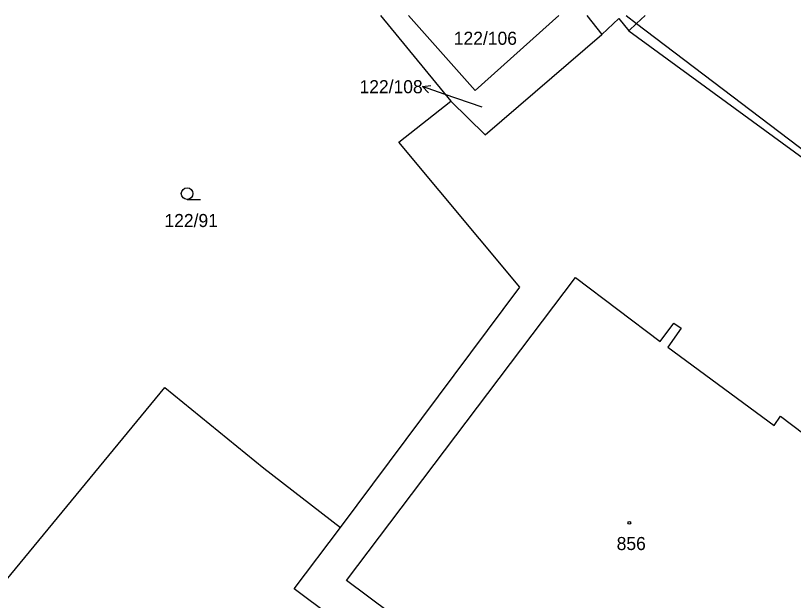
# Model space of a CAD drawing. Extents: x -805057 to -804930, y -994399 to -994240.
# Drawn here: x -804999.86 to -804979.61, y -994258.38 to -994243.17 of the extents above; entities that cross this region are included whole.
import ezdxf

# ---------------------------------------------------------------- set-up
doc = ezdxf.new("R2010")
doc.units = 0
doc.layers.add('Katastralni mapa', color=7, linetype='Continuous')

msp = doc.modelspace()

# ---------------------------------------------------------------- linework, layer by layer
at = {"layer": 'Katastralni mapa'}
for points in [[(-804990.359, -994243.17), (-804988.53, -994245.4)], [(-804987.89, -994245.12), (-804989.625, -994243.17)], [(-804987.89, -994245.12), (-804985.714, -994243.17)], [(-804984.989, -994243.17), (-804984.6, -994243.66)], [(-804983.965, -994243.17), (-804983.69, -994243.38)], [(-804983.69, -994243.38), (-804983.469, -994243.17)], [(-804984.6, -994243.66), (-804984.15, -994243.25)], [(-804984.15, -994243.25), (-804983.89, -994243.57)], [(-804983.89, -994243.57), (-804983.69, -994243.38)], [(-804983.69, -994243.38), (-804969.78, -994253.93)], [(-804983.89, -994243.57), (-804976.36, -994249.06)], [(-804987.63, -994246.27), (-804984.6, -994243.66)], [(-804989.11, -994245.175), (-804989.267, -994245.015), (-804989.046, -994244.985)], [(-804988.7, -994245.21), (-804989.267, -994245.015)], [(-804989.88, -994246.46), (-804988.53, -994245.4)], [(-804987.71, -994245.55), (-804988.7, -994245.21)], [(-804988.53, -994245.4), (-804987.63, -994246.27)], [(-804986.73, -994250.23), (-804989.88, -994246.46)], [(-804995.39, -994247.95), (-804995.039, -994247.95)], [(-804991.24, -994257.86), (-804985.28, -994249.98)], [(-804985.28, -994249.98), (-804983.08, -994251.65)], [(-804991.4, -994256.48), (-804986.73, -994250.23)], [(-804983.08, -994251.65), (-804982.72, -994251.17)], [(-804982.72, -994251.17), (-804982.53, -994251.3)], [(-804982.53, -994251.3), (-804982.88, -994251.79)], [(-804982.88, -994251.79), (-804980.11, -994253.83)], [(-805000.1, -994257.85), (-804995.97, -994252.84)], [(-804995.97, -994252.84), (-804993.39, -994254.94)], [(-804980.11, -994253.83), (-804979.95, -994253.59)], [(-804979.95, -994253.59), (-804975.52, -994256.93)], [(-804993.39, -994254.94), (-804991.4, -994256.48)], [(-804992.6, -994258.08), (-804991.4, -994256.48)], [(-804984.51, -994262.88), (-804991.24, -994257.86)], [(-804985.11, -994263.68), (-804992.6, -994258.08)]]:
    msp.add_lwpolyline(points, dxfattribs=at)
for centre, radius in [((-804995.39, -994247.8), 0.151), ((-804983.88, -994256.36), 0.0355)]:
    msp.add_circle(centre, radius, dxfattribs=at)

# ---------------------------------------------------------------- texts
for s, p in [('122/106', (-804988.449, -994243.93)), ('122/108', (-804990.903, -994245.19)), ('122/91', (-804995.98, -994248.67)), ('856', (-804984.21, -994257.07))]:
    msp.add_text(s, height=0.34, dxfattribs=at).set_placement(p)

doc.saveas('drawing.dxf')
